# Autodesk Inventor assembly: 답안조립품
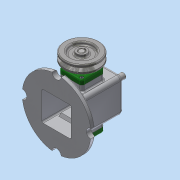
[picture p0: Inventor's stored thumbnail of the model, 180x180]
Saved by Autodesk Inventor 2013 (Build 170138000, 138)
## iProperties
Created: 2018-07
Part Number: 답안조립품
Document SubType Name: Assembly
Designer: Administrator
Author: Administrator
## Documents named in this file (16)
- C:\Users\Administrator\Desktop\480708V1002\답안조립품.iam
- C:\Users\Administrator\Desktop\480708V1002\V벨트풀리.ipt
- C:\Users\Administrator\Desktop\480708V1002\고정핀 1.2x8.ipt
- C:\Users\Administrator\Desktop\480708V1002\뒤커버.ipt
- C:\Users\Administrator\Desktop\480708V1002\링크.ipt
- C:\Users\Administrator\Desktop\480708V1002\멈춤나사 M3x8.ipt
- C:\Users\Administrator\Desktop\480708V1002\베어링 12x32x10.ipt
- C:\Users\Administrator\Desktop\480708V1002\본체.ipt
- C:\Users\Administrator\Desktop\480708V1002\볼트 M4.ipt
- C:\Users\Administrator\Desktop\480708V1002\부시.ipt
- C:\Users\Administrator\Desktop\480708V1002\슬라이드.ipt
- C:\Users\Administrator\Desktop\480708V1002\앞커버.ipt
- C:\Users\Administrator\Desktop\480708V1002\오일 실 12 25 7.ipt
- C:\Users\Administrator\Desktop\480708V1002\키 4x4x10.ipt
- C:\Users\Administrator\Desktop\480708V1002\편심축.ipt
- C:\Users\Administrator\Desktop\480708V1002\핀 5x18.ipt
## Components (3 placed, 3 different names)
1. V벨트풀리:1 — 플러쉬:2
2. 고정핀 1.2x8:1
3. 핀 5x18:1
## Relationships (1: Flush 1)
- 플러쉬:2 [Flush]: V벨트풀리:1
